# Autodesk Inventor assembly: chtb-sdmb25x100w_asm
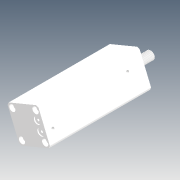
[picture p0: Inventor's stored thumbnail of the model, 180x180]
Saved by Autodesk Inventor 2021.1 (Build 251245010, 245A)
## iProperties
Company: Microsoft
Created: 2018-05
Part Number: chtb-sdmb25x100w_asm
Description: STEP AP214
Document SubType Name: Assembly
Designer: user
Title: chtb-sdmb25x100w_asm.STEP
Author: Windows
Revision Number: ÈÎºÎ
Sending System: SolidWorks 2015
Preprocessor: SwSTEP 2.0
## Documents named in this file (4)
- D:\Vault_2016\Projekty\Clamptek\Hydraulic\CHTB\CHTB-25\Inventor\chtb-sdmb25x100w\chtb-sdmb25x100w_asm.iam
- D:\Vault_2016\Projekty\Clamptek\Hydraulic\CHTB\CHTB-25\Inventor\chtb-sdmb25x100w\CHTB-25QG.ipt
- D:\Vault_2016\Projekty\Clamptek\Hydraulic\CHTB\CHTB-25\Inventor\chtb-sdmb25x100w\CHTB-SDMB25X100NBT.ipt
- D:\Vault_2016\Projekty\Clamptek\Hydraulic\CHTB\CHTB-25\Inventor\chtb-sdmb25x100w\CHTB-SDMB25X100WHSG.ipt
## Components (3 placed, 3 different names)
1. CHTB-25QG_1
2. CHTB-SDMB25X100NBT_2
3. CHTB-SDMB25X100WHSG_3
